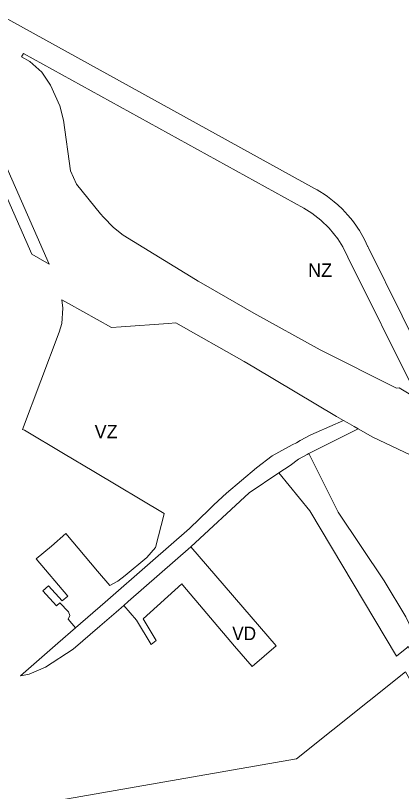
# Model space of a CAD drawing. Extents: x -650451 to -642268, y -1075216 to -1066610.
# Drawn here: x -646501 to -646157, y -1069167 to -1068476 of the extents above; entities that cross this region are included whole.
import ezdxf

# ---------------------------------------------------------------- set-up
doc = ezdxf.new("R2010")
doc.units = 0
doc.header["$LTSCALE"] = 4.8
for name, color, linetype, lineweight in [('15', 7, 'Continuous', 13), ('24', 7, 'Continuous', 13), ('35', 7, 'Continuous', 13), ('36', 7, 'Continuous', 13), ('46', 7, 'Continuous', 13)]:
    doc.layers.add(name, color=color, linetype=linetype, lineweight=lineweight)
doc.layers.add('62', color=7, linetype='Continuous')

msp = doc.modelspace()

# ---------------------------------------------------------------- linework, layer by layer
at = {"layer": '15'}
for points in [[(-646266.118, -1068883.048), (-646256.13, -1068876.42), (-646248.82, -1068870.79), (-646241.07, -1068866.67), (-646239.43, -1068865.79)], [(-646239.43, -1068865.79), (-646213.25, -1068917.87), (-646172.32, -1068979.11), (-646153.2, -1069011.21), (-646103.59, -1069114.91)], [(-646161.484, -1069046.228), (-646238.632, -1068916.799), (-646266.118, -1068883.048)], [(-646017.15, -1069280.19), (-646037.99, -1069242.88), (-646107, -1069119.41), (-646150.87, -1069037.64), (-646152.26, -1069038.76), (-646161.484, -1069046.228)]]:
    msp.add_lwpolyline(points, dxfattribs=at)
at = {"layer": '24'}
for points in [[(-646545.57, -1068511.42), (-646541.06, -1068524.58), (-646535.84, -1068539.8), (-646521.81, -1068580.69), (-646519.14, -1068587.06), (-646516.07, -1068595.08), (-646515.09, -1068597.29), (-646470.65, -1068697.38), (-646486.23, -1068688.54)], [(-646486.23, -1068688.54), (-646526.1, -1068598.55), (-646555, -1068519.38), (-646556.22, -1068515.84)], [(-646447.2, -1069020.9), (-646420.96, -1068998.03), (-646380.88, -1068963.08), (-646345.87, -1068932.56), (-646328.28, -1068915.58), (-646324.04, -1068911.62), (-646312.72, -1068901.07), (-646286.22, -1068878.44), (-646272.13, -1068867.84), (-646254.36, -1068858.21), (-646250.58, -1068856.16), (-646247.14, -1068854.3), (-646237.82, -1068849.24), (-646232.81, -1068847.24), (-646208.7, -1068836.39)], [(-646208.7, -1068836.39), (-646205.48, -1068838.23), (-646199.24, -1068841.79), (-646195.52, -1068843.92), (-646239.43, -1068865.79)], [(-646239.43, -1068865.79), (-646241.07, -1068866.67), (-646248.82, -1068870.79), (-646256.13, -1068876.42), (-646266.118, -1068883.048)], [(-646266.118, -1068883.048), (-646292.75, -1068900.72), (-646344.49, -1068948.736)], [(-646344.49, -1068948.736), (-646400.39, -1068997.58), (-646404.269, -1069001.033)], [(-646404.269, -1069001.033), (-646410.96, -1069006.99), (-646425.52, -1069019.41), (-646449.419, -1069039.805), (-646474.13, -1069055.83), (-646488.537, -1069062.169), (-646495.89, -1069063.531), (-646496.317, -1069063.61)], [(-646496.317, -1069063.61), (-646462.98, -1069034.61), (-646447.2, -1069020.9)]]:
    msp.add_lwpolyline(points, dxfattribs=at)
at = {"layer": '35'}
for points in [[(-646404.269, -1069001.033), (-646400.39, -1068997.58), (-646344.49, -1068948.736)], [(-646344.49, -1068948.736), (-646268.528, -1069036.82), (-646290.099, -1069055.423), (-646305.65, -1069037.39), (-646351.641, -1068983.083), (-646351.638, -1068983.08), (-646352.71, -1068981.82), (-646386.936, -1069012.936), (-646375.346, -1069032.07), (-646379.973, -1069035.889), (-646393.09, -1069014.234), (-646404.269, -1069001.033)]]:
    msp.add_lwpolyline(points, dxfattribs=at)
at = {"layer": '36'}
for points in [[(-646494.52, -1068844.29), (-646461.92, -1068757.93), (-646459.59, -1068750.19), (-646458.57, -1068736.31), (-646459.54, -1068728.94), (-646453.51, -1068732.3), (-646415.3, -1068753.62), (-646406.7, -1068753.03), (-646364.77, -1068750.16), (-646357.87, -1068749.64)], [(-646357.87, -1068749.64), (-646297.08, -1068783.8), (-646288.37, -1068789.04), (-646251.73, -1068811.04), (-646214.92, -1068832.85), (-646208.7, -1068836.39)], [(-646208.7, -1068836.39), (-646232.81, -1068847.24), (-646237.82, -1068849.24), (-646247.14, -1068854.3), (-646250.58, -1068856.16), (-646254.36, -1068858.21), (-646272.13, -1068867.84), (-646286.22, -1068878.44), (-646312.72, -1068901.07), (-646324.04, -1068911.62), (-646328.28, -1068915.58), (-646345.87, -1068932.56), (-646380.88, -1068963.08), (-646420.96, -1068998.03), (-646447.2, -1069020.9)], [(-646447.2, -1069020.9), (-646453.88, -1069013.1), (-646452.37, -1069010.01), (-646453.48, -1069006.75), (-646461.29, -1068998.81), (-646464.24, -1069001.49), (-646476.35, -1068987.98), (-646471.24, -1068983.41), (-646459.25, -1068996.98), (-646454.21, -1068992.73), (-646482.2, -1068959.52), (-646468.83, -1068948.26), (-646455.78, -1068936.87), (-646427.77, -1068970.39), (-646416.71, -1068983.21), (-646409.67, -1068979.3), (-646403.13, -1068974.41), (-646383.86, -1068958.24), (-646376.02, -1068949.34), (-646368.42, -1068919.59), (-646368.3, -1068919.19), (-646430.86, -1068881.89), (-646457.86, -1068865.8), (-646492.73, -1068845.01), (-646494.52, -1068844.29)]]:
    msp.add_lwpolyline(points, dxfattribs=at)
at = {"layer": '46'}
for p, q in [((-646495.416, -1068512.888), (-646493.511, -1068509.855)), ((-646239.43, -1068865.79), (-646195.52, -1068843.92))]:
    msp.add_line(p, q, dxfattribs=at)
for points in [[(-646126.317, -1068803.654), (-646186.371, -1068682.825), (-646186.901, -1068681.614), (-646187.091, -1068681.19), (-646189.676, -1068675.819), (-646191.425, -1068672.562), (-646192.895, -1068670.012), (-646194.492, -1068667.409), (-646195.834, -1068665.339), (-646197.683, -1068662.645), (-646199.218, -1068660.531), (-646200.727, -1068658.552), (-646202.389, -1068656.475), (-646204.769, -1068653.669), (-646207.455, -1068650.718), (-646209.607, -1068648.501), (-646213.784, -1068644.532), (-646216.809, -1068641.902), (-646219.751, -1068639.522), (-646222.933, -1068637.129), (-646225.838, -1068635.097), (-646229.573, -1068632.68), (-646232.141, -1068631.139), (-646234.342, -1068629.892), (-646513.45, -1068476.025)], [(-646150.26, -1068812.81), (-646159.1, -1068807.43), (-646161.45, -1068807.54), (-646229.44, -1068773.53), (-646288.59, -1068740.88), (-646331.26, -1068716.25), (-646337.93, -1068712.4), (-646340.36, -1068710.915), (-646404.83, -1068671.52), (-646413.45, -1068664.71), (-646422.32, -1068655.58), (-646425.11, -1068652.37), (-646446.54, -1068626.14), (-646451.82, -1068614.31), (-646458.03, -1068569.26), (-646461.14, -1068556.34), (-646469.51, -1068538.15), (-646477.41, -1068526.45), (-646487.92, -1068516.87), (-646495.416, -1068512.888)], [(-646493.511, -1068509.855), (-646243.997, -1068647.407), (-646236.707, -1068651.891), (-646228.691, -1068658.051), (-646221.348, -1068665.144), (-646213.659, -1068674.696), (-646209.179, -1068681.795), (-646204.654, -1068690.937), (-646145.083, -1068810.83), (-646150.26, -1068812.81)], [(-646195.52, -1068843.92), (-646182.57, -1068851.3), (-646137.23, -1068872.6)], [(-646103.59, -1069114.91), (-646153.2, -1069011.21), (-646172.32, -1068979.11), (-646213.25, -1068917.87), (-646239.43, -1068865.79)], [(-646626.774, -1069359.349), (-646611.107, -1069309.68), (-646577.878, -1069206.485), (-646572.586, -1069194.485), (-646569.114, -1069188.86), (-646526.31, -1069184.381), (-646479.84, -1069177.626), (-646250.409, -1069137.52), (-646153.307, -1069059.947), (-646025.14, -1069285.394)]]:
    msp.add_lwpolyline(points, dxfattribs=at)

# ---------------------------------------------------------------- texts
at = {"layer": '62'}
for s, p in [('NZ', (-646240.156, -1068708.695)), ('VZ', (-646430.272, -1068852.285))]:
    msp.add_text(s, height=12, dxfattribs=at).set_placement(p)
at = {"layer": '62', "width": 0.95}
msp.add_text('VD', height=12, dxfattribs=at).set_placement((-646307.658, -1069031.906))

doc.saveas('drawing.dxf')
